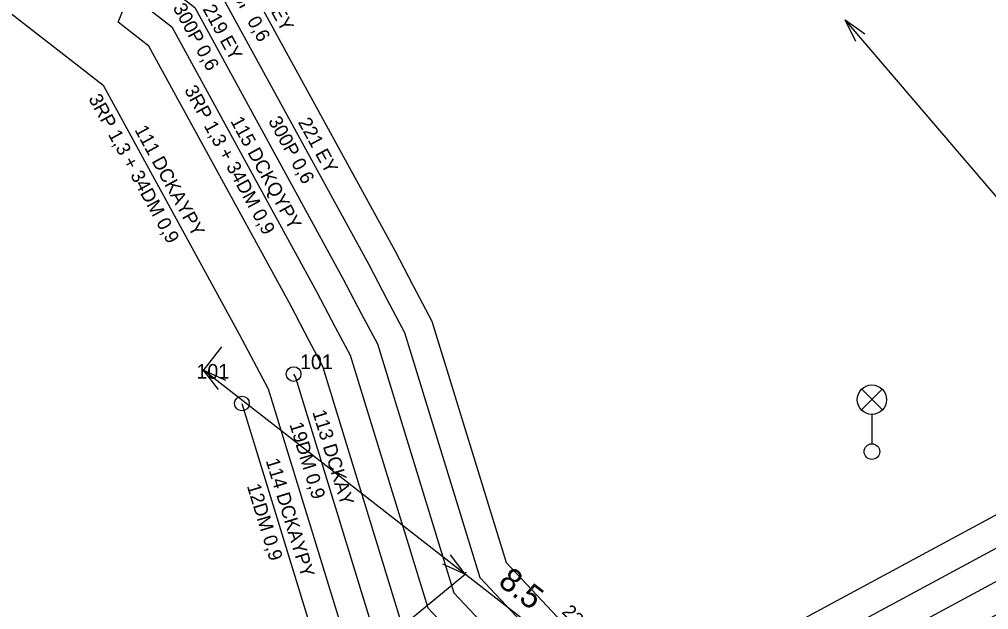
# Model space of a CAD drawing. Extents: x -756413 to -755757, y -1139003 to -1138237.
# Drawn here: x -756268.25 to -756243.52, y -1138322.62 to -1138307.56 of the extents above; entities that cross this region are included whole.
import ezdxf

# ---------------------------------------------------------------- set-up
doc = ezdxf.new("R2010")
doc.units = 0
for name, color, linetype in [('f002_inz_znacky_mimo_TO2', 7, 'Continuous'), ('f006_osa_trasy', 7, 'Continuous'), ('f006_stp_koty', 7, 'Continuous'), ('f307_kabel_metal', 7, 'Continuous'), ('f307_kabel_metal_ann', 7, 'Continuous'), ('f307_spojka_metal', 7, 'Continuous'), ('f307_spojka_metal_ann', 7, 'Continuous')]:
    doc.layers.add(name, color=color, linetype=linetype)

msp = doc.modelspace()

# ---------------------------------------------------------------- linework, layer by layer
at = {"layer": 'f002_inz_znacky_mimo_TO2'}
for p, q in [((-756246.764, -1138317.528), (-756246.236, -1138317)), ((-756246.228, -1138317.525), (-756246.756, -1138316.996)), ((-756246.5, -1138317.64), (-756246.5, -1138318.39))]:
    msp.add_line(p, q, dxfattribs=at)
for centre, radius in [((-756246.5, -1138317.265), 0.375), ((-756246.5, -1138318.59), 0.2)]:
    msp.add_circle(centre, radius, dxfattribs=at)
at = {"layer": 'f006_osa_trasy'}
msp.add_lwpolyline([(-756253.74, -1138329.49), (-756254.57, -1138328.56), (-756258.6, -1138324.18), (-756259.14, -1138323.58), (-756256.88, -1138321.72)], dxfattribs=at)
at = {"layer": 'f006_stp_koty'}
for p, q in [((-756234.87, -1138321.97), (-756247.183, -1138307.573)), ((-756263.089, -1138315.92), (-756263.591, -1138316.564)), ((-756255.242, -1138322.993), (-756263.554, -1138316.516)), ((-756256.881, -1138321.716), (-756256.844, -1138321.669))]:
    msp.add_line(p, q, dxfattribs=at)
for points in [[(-756246.907, -1138308.126), (-756247.183, -1138307.573), (-756246.679, -1138307.931)], [(-756263.172, -1138317.003), (-756263.554, -1138316.516), (-756262.988, -1138316.766)], [(-756257.262, -1138321.228), (-756256.881, -1138321.716), (-756257.446, -1138321.465)]]:
    msp.add_lwpolyline(points, dxfattribs=at)
at = {"layer": 'f307_kabel_metal'}
for points in [[(-756306.485, -1138287.215), (-756299.649, -1138292.651), (-756293.451, -1138294.434), (-756292.208, -1138293.55), (-756284.024, -1138291.942), (-756268.721, -1138301.5), (-756268.17, -1138301.844), (-756267.146, -1138302.732), (-756266.635, -1138303.13), (-756265.943, -1138303.667), (-756265.338, -1138304.142), (-756262.609, -1138306.261), (-756258.674, -1138313.461), (-756258.2, -1138314.363), (-756257.724, -1138315.263), (-756255.834, -1138321.418), (-756252.314, -1138325.16), (-756248.718, -1138323.124), (-756248.03, -1138322.735), (-756238.36, -1138317.525), (-756232.54, -1138311.52), (-756229.485, -1138308.375), (-756222.9, -1138304.16), (-756217, -1138310.915)], [(-756254.548, -1138330.753), (-756252.529, -1138329.851), (-756253.612, -1138328.339), (-756254.031, -1138327.712), (-756254.111, -1138327.627), (-756258.498, -1138322.966), (-756260.508, -1138316.415), (-756260.852, -1138315.763), (-756261.318, -1138314.88), (-756264.942, -1138308.248), (-756265.731, -1138307.633), (-756260.833, -1138295.634)], [(-756268.617, -1138302.449), (-756267.622, -1138303.312), (-756267.095, -1138303.722), (-756266.405, -1138304.258), (-756265.8, -1138304.733), (-756263.192, -1138306.758), (-756259.335, -1138313.815), (-756258.863, -1138314.713), (-756258.42, -1138315.551), (-756256.5, -1138321.805), (-756252.488, -1138326.069), (-756252.318, -1138326.024), (-756248.349, -1138323.777), (-756247.668, -1138323.392), (-756237.902, -1138318.13), (-756232.002, -1138312.042), (-756229.008, -1138308.96), (-756223.04, -1138305.14), (-756217.578, -1138311.394)], [(-756269.064, -1138303.054), (-756268.098, -1138303.892), (-756267.555, -1138304.314), (-756266.867, -1138304.849), (-756266.261, -1138305.324), (-756263.775, -1138307.255), (-756259.996, -1138314.17), (-756259.526, -1138315.063), (-756259.116, -1138315.839), (-756257.166, -1138322.192), (-756253.02, -1138326.598), (-756252.904, -1138326.72), (-756252.717, -1138326.908), (-756252.031, -1138326.723), (-756247.98, -1138324.43), (-756247.306, -1138324.049), (-756237.444, -1138318.735), (-756231.464, -1138312.564), (-756228.531, -1138309.545), (-756223.18, -1138306.12), (-756218.156, -1138311.873)], [(-756270.31, -1138304.044), (-756269.958, -1138304.264), (-756269.051, -1138305.051), (-756268.476, -1138305.498), (-756266.3, -1138307.19), (-756265.977, -1138306.494), (-756264.358, -1138307.752), (-756260.657, -1138314.525), (-756260.189, -1138315.413), (-756259.812, -1138316.127), (-756257.832, -1138322.579), (-756253.565, -1138327.113), (-756253.442, -1138327.243), (-756252.94, -1138327.745), (-756251.744, -1138327.422), (-756247.611, -1138325.083), (-756246.944, -1138324.706), (-756236.986, -1138319.34), (-756230.926, -1138313.086), (-756228.054, -1138310.13), (-756223.32, -1138307.1), (-756218.734, -1138312.352)], [(-756270.019, -1138306.197), (-756266.653, -1138308.817), (-756266.11, -1138309.24), (-756262.64, -1138315.59), (-756261.9, -1138316.99), (-756259.83, -1138323.74), (-756255.203, -1138328.655), (-756254.69, -1138329.2), (-756254.31, -1138329.67), (-756251.17, -1138328.82), (-756246.873, -1138326.389), (-756246.22, -1138326.02), (-756236.07, -1138320.55), (-756229.85, -1138314.13), (-756227.1, -1138311.3), (-756223.6, -1138309.06), (-756219.89, -1138313.31), (-756204.84, -1138332.43), (-756204.754, -1138332.538), (-756193.708, -1138346.394), (-756193.24, -1138346.98), (-756191.54, -1138349.16)], [(-756261.252, -1138316.611), (-756261.204, -1138316.702), (-756259.164, -1138323.353), (-756254.657, -1138328.141), (-756254.125, -1138328.707), (-756254.034, -1138328.818), (-756251.457, -1138328.121), (-756247.242, -1138325.736), (-756246.582, -1138325.363), (-756236.528, -1138319.945), (-756230.388, -1138313.608), (-756227.577, -1138310.715), (-756223.46, -1138308.08), (-756219.312, -1138312.831), (-756204.252, -1138331.964), (-756204.167, -1138332.071), (-756193.122, -1138345.926), (-756192.651, -1138346.515), (-756190.949, -1138348.699), (-756183.432, -1138357.122)], [(-756262.57, -1138317.363), (-756260.496, -1138324.127), (-756259.505, -1138325.18), (-756259.777, -1138325.43), (-756263.526, -1138328.915), (-756272.962, -1138335.593), (-756279.837, -1138339.642), (-756286.212, -1138342.863), (-756292.891, -1138344.13), (-756301.068, -1138343.923), (-756309.263, -1138342.52), (-756313.137, -1138339.946), (-756313.333, -1138340.073), (-756320.121, -1138347.951), (-756315.62, -1138351.591), (-756312.901, -1138354.115), (-756327.623, -1138366.698), (-756326.363, -1138368.116), (-756330.364, -1138371.464)]]:
    msp.add_lwpolyline(points, dxfattribs=at)
at = {"layer": 'f307_spojka_metal'}
for centre in [(-756261.252, -1138316.611), (-756262.57, -1138317.363)]:
    msp.add_circle(centre, 0.188, dxfattribs=at)

# ---------------------------------------------------------------- texts
at = {"layer": 'f006_stp_koty'}
msp.add_text('8.5', height=0.6, rotation=322.08, dxfattribs=at).set_placement((-756256.063, -1138321.972))
at = {"layer": 'f307_kabel_metal_ann'}
for s, rotation, p in [(' 300P 0,6', 298.66, (-756263.098, -1138306.41)), ('224 EY', 298.66, (-756262.277, -1138306.557)), (' 300P 0,6', 298.66, (-756264.403, -1138307.148)), ('219 EY', 298.66, (-756263.582, -1138307.295)), (' 3RP 1,3 + 34DM 0,9', 298.65, (-756264.112, -1138309.244)), (' 3RP 1,3 + 34DM 0,9', 298.65, (-756266.556, -1138309.466)), ('115 DCKQYPY', 298.65, (-756262.875, -1138310.153)), (' 300P 0,6', 298.66, (-756261.971, -1138310.035)), ('221 EY', 298.66, (-756261.15, -1138310.182)), ('111 DCKAYPY', 298.65, (-756265.319, -1138310.375)), ('113 DCKAY', 287.05, (-756260.777, -1138317.581)), (' 19DM 0,9', 287.05, (-756261.399, -1138317.77)), ('114 DCKAYPY', 287.05, (-756261.966, -1138318.82)), (' 12DM 0,9', 287.05, (-756262.486, -1138319.341)), ('224 EY', 313.25, (-756254.427, -1138322.696))]:
    msp.add_text(s, height=0.35, rotation=rotation, dxfattribs=at).set_placement(p)
at = {"layer": 'f307_spojka_metal_ann'}
for p in [(-756261.089, -1138316.486), (-756263.732, -1138316.73)]:
    msp.add_text('101', height=0.375, dxfattribs=at).set_placement(p)

doc.saveas('drawing.dxf')
